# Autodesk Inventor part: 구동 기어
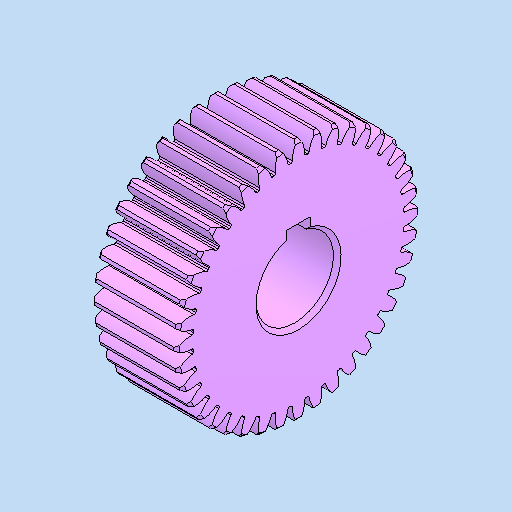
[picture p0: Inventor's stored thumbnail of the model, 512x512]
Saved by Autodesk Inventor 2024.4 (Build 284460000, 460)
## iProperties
Created: 2025-11
Part Number: 구동 기어
Material: 강철, 합금
Document SubType Name: Modeling
Designer: home
Density: 7.73 g/cm^3
Appearance: 기본값
Author: jhkim
Sending System: Autodesk Inventor 2026
Preprocessor: ST-DEVELOPER v20.1
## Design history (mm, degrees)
feature "솔리드1"
node "솔리드2"
